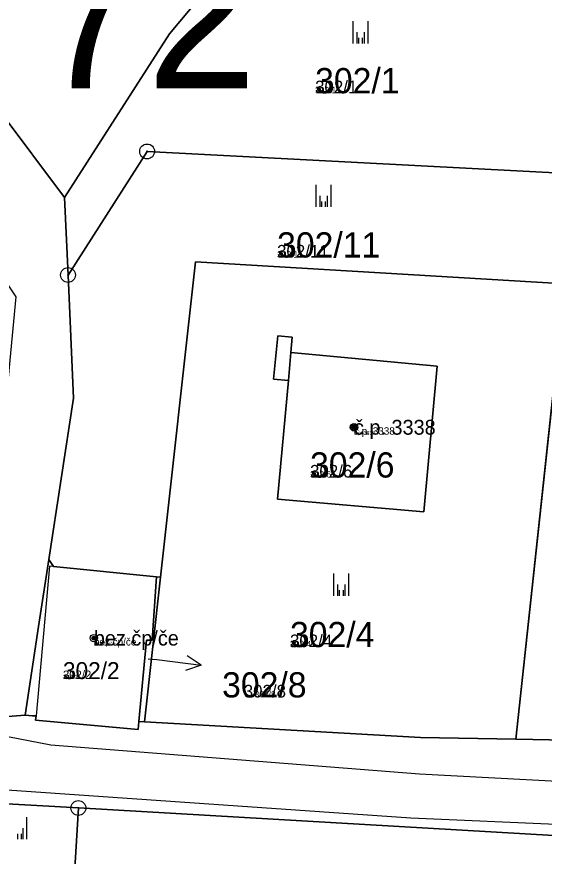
# Model space of a CAD drawing. Extents: x -759873 to -758487, y -975024 to -973516.
# Drawn here: x -759035.8 to -759000.3, y -974362.2 to -974305.6 of the extents above; entities that cross this region are included whole.
import ezdxf

# ---------------------------------------------------------------- set-up
doc = ezdxf.new("R2010")
doc.units = 0
for name, color, linetype in [('KAT_02_hranice parcel', 7, 'Continuous'), ('KAT_03_1000_st čísla parcelní', 7, 'Continuous'), ('KAT_03_1000_čísla parcelní', 7, 'Continuous'), ('KAT_03_1000_čísla popisná', 7, 'Continuous'), ('KAT_03_250_st čísla parcelní', 7, 'Continuous'), ('KAT_03_250_čísla parcelní', 7, 'Continuous'), ('KAT_03_250_čísla popisná', 7, 'Continuous'), ('KAT_03_500_st čísla parcelní', 7, 'Continuous'), ('KAT_03_500_čísla parcelní', 7, 'Continuous'), ('KAT_03_500_čísla popisná', 7, 'Continuous'), ('KAT_04_vnitřní kresba', 7, 'Continuous'), ('KAT_05_1000_značky kultur', 7, 'Continuous'), ('KAT_05_250_značky kultur', 7, 'Continuous'), ('KAT_05_500_značky kultur', 7, 'Continuous'), ('KAT_07_1000_značky budov', 7, 'Continuous'), ('KAT_07_250_značky budov', 7, 'Continuous'), ('KAT_07_500_značky budov', 7, 'Continuous'), ('KAT_11_značky bodu BP', 7, 'Continuous'), ('KAT_12_pomocná šipka', 7, 'Continuous'), ('KAT_13_popis', 7, 'Continuous'), ('KAT_14_plocha_budovy', 7, 'Continuous'), ('KAT_14_plocha_pozemek', 7, 'Continuous')]:
    doc.layers.add(name, color=color, linetype=linetype)

msp = doc.modelspace()

# ---------------------------------------------------------------- linework, layer by layer
at = {"layer": 'KAT_02_hranice parcel'}
for p, q in [((-759032.56, -974317.79), (-759032.33, -974323.02)), ((-758998.87, -974323.61), (-759002.18, -974354.31)), ((-759026.1, -974343.38), (-759026.37, -974343.35)), ((-759026.1, -974343.38), (-759027.18, -974353.14)), ((-759035.22, -974352.69), (-759041.4, -974353.16)), ((-759027.18, -974353.14), (-759027.55, -974353.12)), ((-758977.12, -974354.79), (-759002.18, -974354.31))]:
    msp.add_line(p, q, dxfattribs=at)
for points in [[(-759057.23, -974110.82), (-759070.93, -974124.94), (-759074.88, -974130.5), (-759080.81, -974167.04), (-759083.49, -974196.85), (-759080.01, -974222.92), (-759077.81, -974236.38), (-759067.25, -974271.4), (-759032.56, -974317.79)], [(-759014.33, -974293.41), (-759025.5, -974306.76), (-759032.56, -974317.79)], [(-759032.33, -974323.02), (-759027, -974314.69), (-758998.23, -974316.19)], [(-758998.87, -974323.61), (-759023.75, -974322.12), (-759026.1, -974343.38)], [(-759032.33, -974323.02), (-759031.96, -974331.33), (-759033.62, -974342.2)], [(-759017.23, -974327.21), (-759017.32, -974328.25), (-759007.46, -974329.16), (-759008.36, -974338.99), (-759018.21, -974338.13), (-759017.49, -974330.13), (-759018.49, -974330.04), (-759018.19, -974327.12), (-759017.23, -974327.21)], [(-759035.22, -974352.69), (-759034.31, -974346.71), (-759033.62, -974342.2)], [(-759026.37, -974343.35), (-759033.3, -974342.67), (-759033.62, -974342.2)], [(-759027.55, -974353.12), (-759027.05, -974347.62), (-759026.67, -974347.64), (-759026.37, -974343.35)], [(-759027.55, -974353.12), (-759027.6, -974353.65), (-759034.51, -974353.02), (-759034.48, -974352.73), (-759034.72, -974352.72), (-759035.22, -974352.69)], [(-759002.18, -974354.31), (-759008.59, -974354.19), (-759027.18, -974353.14)], [(-759031.63, -974358.94), (-759032.43, -974372.28), (-759040.64, -974371.84), (-759039.97, -974358.1)], [(-759039.97, -974358.1), (-759037.67, -974358.59), (-759031.63, -974358.94)], [(-759031.63, -974358.94), (-758978.01, -974362.06), (-758930.04, -974363.17)]]:
    msp.add_lwpolyline(points, dxfattribs=at)
at = {"layer": 'KAT_03_1000_čísla popisná'}
for centre in [(-759013.07, -974333.28), (-759030.59, -974347.49)]:
    msp.add_circle(centre, 0.25, dxfattribs=at)
at = {"layer": 'KAT_03_250_čísla popisná'}
for centre in [(-759013.07, -974333.28), (-759030.59, -974347.49)]:
    msp.add_circle(centre, 0.0625, dxfattribs=at)
at = {"layer": 'KAT_03_500_čísla popisná'}
for centre in [(-759013.07, -974333.28), (-759030.59, -974347.49)]:
    msp.add_circle(centre, 0.125, dxfattribs=at)
at = {"layer": 'KAT_04_vnitřní kresba'}
for p, q in [((-759017.49, -974330.13), (-759017.32, -974328.25)), ((-759033.57, -974342.64), (-759034.48, -974352.73)), ((-759033.3, -974342.67), (-759033.57, -974342.64)), ((-759041.4, -974353.16), (-759033.48, -974354.69)), ((-759033.48, -974354.69), (-759008.66, -974356.64)), ((-759008.66, -974356.64), (-758988.32, -974357.74)), ((-759040.71, -974357.41), (-759009.25, -974359.61)), ((-759009.25, -974359.61), (-758949.37, -974362.15))]:
    msp.add_line(p, q, dxfattribs=at)
at = {"layer": 'KAT_05_1000_značky kultur'}
for p, q in [((-759013.121, -974307.41), (-759013.121, -974305.91)), ((-759012.12, -974307.41), (-759012.12, -974305.91)), ((-759015.611, -974318.43), (-759015.611, -974316.93)), ((-759014.61, -974318.43), (-759014.61, -974316.93)), ((-759014.421, -974344.63), (-759014.421, -974343.13)), ((-759013.42, -974344.63), (-759013.42, -974343.13)), ((-759035.1, -974361.05), (-759035.1, -974359.55))]:
    msp.add_line(p, q, dxfattribs=at)
at = {"layer": 'KAT_05_250_značky kultur'}
for p, q in [((-759012.738, -974307.41), (-759012.738, -974307.035)), ((-759012.488, -974307.41), (-759012.488, -974307.035)), ((-759015.228, -974318.43), (-759015.228, -974318.055)), ((-759014.978, -974318.43), (-759014.978, -974318.055)), ((-759014.038, -974344.63), (-759014.038, -974344.255)), ((-759013.787, -974344.63), (-759013.787, -974344.255)), ((-759035.718, -974361.05), (-759035.718, -974360.675)), ((-759035.468, -974361.05), (-759035.468, -974360.675))]:
    msp.add_line(p, q, dxfattribs=at)
at = {"layer": 'KAT_05_500_značky kultur'}
for p, q in [((-759012.866, -974307.41), (-759012.866, -974306.66)), ((-759012.365, -974307.41), (-759012.365, -974306.66)), ((-759015.356, -974318.43), (-759015.356, -974317.68)), ((-759014.855, -974318.43), (-759014.855, -974317.68)), ((-759014.166, -974344.63), (-759014.166, -974343.88)), ((-759013.665, -974344.63), (-759013.665, -974343.88)), ((-759035.345, -974361.05), (-759035.345, -974360.3))]:
    msp.add_line(p, q, dxfattribs=at)
at = {"layer": 'KAT_07_1000_značky budov'}
for centre, radius in [((-759013.077, -974333.279), 0.175), ((-759030.595, -974347.489), 0.117)]:
    msp.add_circle(centre, radius, dxfattribs=at)
at = {"layer": 'KAT_07_250_značky budov'}
for centre, radius in [((-759013.072, -974333.28), 0.0437), ((-759030.591, -974347.49), 0.0293)]:
    msp.add_circle(centre, radius, dxfattribs=at)
at = {"layer": 'KAT_07_500_značky budov'}
for centre, radius in [((-759013.073, -974333.28), 0.0875), ((-759030.592, -974347.49), 0.0586)]:
    msp.add_circle(centre, radius, dxfattribs=at)
at = {"layer": 'KAT_11_značky bodu BP'}
for centre, radius in [((-759027, -974314.69), 0.5), ((-759027, -974314.69), 0.0303), ((-759032.33, -974323.02), 0.5), ((-759032.33, -974323.02), 0.0303), ((-759031.63, -974358.94), 0.5), ((-759031.63, -974358.94), 0.0303)]:
    msp.add_circle(centre, radius, dxfattribs=at)
at = {"layer": 'KAT_12_pomocná šipka'}
for p, q in [((-759026.94, -974348.88), (-759026.34, -974348.94)), ((-759026.34, -974348.94), (-759023.361, -974349.306)), ((-759023.361, -974349.306), (-759024.294, -974348.687)), ((-759023.361, -974349.306), (-759024.416, -974349.681))]:
    msp.add_line(p, q, dxfattribs=at)
at = {"layer": 'KAT_14_plocha_budovy'}
for points in [[(-759018.21, -974338.13), (-759008.36, -974338.99), (-759007.46, -974329.16), (-759017.32, -974328.25), (-759017.49, -974330.13)], [(-759034.51, -974353.02), (-759027.6, -974353.65), (-759027.55, -974353.12), (-759027.05, -974347.62), (-759026.67, -974347.64), (-759026.37, -974343.35), (-759033.3, -974342.67), (-759033.57, -974342.64), (-759034.48, -974352.73)]]:
    msp.add_lwpolyline(points, close=True, dxfattribs=at)
at = {"layer": 'KAT_14_plocha_pozemek'}
for points in [[(-759077.81, -974236.38), (-759067.25, -974271.4), (-759032.56, -974317.79), (-759025.5, -974306.76), (-759014.33, -974293.41), (-759017.69, -974290.39), (-759006.93, -974283.66), (-759032.75, -974249.27), (-759049.48, -974222.24), (-759060.12, -974196.25), (-759061.42, -974162.34), (-759060.75, -974132.98), (-759057.23, -974110.82), (-759070.93, -974124.94), (-759074.88, -974130.5), (-759080.81, -974167.04), (-759083.49, -974196.85), (-759080.01, -974222.92)], [(-758997.18, -974304.01), (-759014.33, -974293.41), (-759025.5, -974306.76), (-759032.56, -974317.79), (-759032.33, -974323.02), (-759027, -974314.69), (-758998.23, -974316.19)], [(-759026.1, -974343.38), (-759023.75, -974322.12), (-758998.87, -974323.61), (-758998.23, -974316.19), (-759027, -974314.69), (-759032.33, -974323.02), (-759031.96, -974331.33), (-759033.62, -974342.2), (-759033.3, -974342.67), (-759026.37, -974343.35)], [(-759026.1, -974343.38), (-759027.18, -974353.14), (-759008.59, -974354.19), (-759002.18, -974354.31), (-758998.87, -974323.61), (-759023.75, -974322.12)], [(-758973.99, -974325.11), (-758998.87, -974323.61), (-759002.18, -974354.31), (-758977.12, -974354.79), (-758975.05, -974336.27)], [(-759017.23, -974327.21), (-759017.32, -974328.25), (-759007.46, -974329.16), (-759008.36, -974338.99), (-759018.21, -974338.13), (-759017.49, -974330.13), (-759018.49, -974330.04), (-759018.19, -974327.12)], [(-759017.23, -974327.21), (-759018.19, -974327.12), (-759018.49, -974330.04), (-759017.49, -974330.13), (-759018.21, -974338.13), (-759008.36, -974338.99), (-759007.46, -974329.16), (-759017.32, -974328.25)], [(-759026.37, -974343.35), (-759033.3, -974342.67), (-759033.62, -974342.2), (-759034.31, -974346.71), (-759035.22, -974352.69), (-759034.72, -974352.72), (-759034.48, -974352.73), (-759034.51, -974353.02), (-759027.6, -974353.65), (-759027.55, -974353.12), (-759027.05, -974347.62), (-759026.67, -974347.64)], [(-759026.1, -974343.38), (-759026.37, -974343.35), (-759026.67, -974347.64), (-759027.05, -974347.62), (-759027.55, -974353.12), (-759027.18, -974353.14)], [(-759040.64, -974371.84), (-759039.97, -974358.1), (-759051.14, -974355.72), (-759056.37, -974366.99), (-759057.32, -974369.03), (-759044.21, -974373.31), (-759031.64, -974374.99), (-759025.9, -974373.3), (-759018.27, -974368.4), (-759006.26, -974363.99), (-758992.93, -974364.06), (-758971.41, -974365.53), (-758952.35, -974369.35), (-758911.81, -974379.4), (-758867.55, -974396.24), (-758881.44, -974386.63), (-758930.04, -974363.17), (-758978.01, -974362.06), (-759031.63, -974358.94), (-759032.43, -974372.28)], [(-759039.97, -974358.1), (-759040.64, -974371.84), (-759032.43, -974372.28), (-759031.63, -974358.94), (-759037.67, -974358.59)]]:
    msp.add_lwpolyline(points, close=True, dxfattribs=at)
for points in [[(-759088.06, -974196.14), (-759086.81, -974208.04), (-759084.6, -974223.26), (-759081.12, -974237.92), (-759079.79, -974238.96), (-759070.66, -974272.52), (-759048.01, -974306.32), (-759035.84, -974324.49), (-759036.24, -974328.76), (-759037.74, -974344.49), (-759041.4, -974353.16), (-759035.22, -974352.69), (-759034.31, -974346.71), (-759033.62, -974342.2), (-759031.96, -974331.33), (-759032.33, -974323.02), (-759032.56, -974317.79), (-759067.25, -974271.4), (-759077.81, -974236.38), (-759080.01, -974222.92), (-759083.49, -974196.85)], [(-759228.43, -974270.82), (-759182.46, -974265.89), (-759176.65, -974264.97), (-759164.95, -974263.13), (-759162.53, -974263.23), (-759159.62, -974263.35), (-759148.86, -974268.28), (-759137.55, -974276.08), (-759137.41, -974276.19), (-759133.42, -974279.5), (-759126.27, -974285.42), (-759121.65, -974289.25), (-759113.88, -974295.69), (-759108.36, -974300.77), (-759091.71, -974319.84), (-759079.48, -974333.82), (-759074.99, -974338.96), (-759070.5, -974344.1), (-759060.98, -974351.22), (-759051.14, -974355.72), (-759039.97, -974358.1), (-759037.67, -974358.59), (-759031.63, -974358.94), (-758978.01, -974362.06)], [(-758977.12, -974354.79), (-759002.18, -974354.31), (-759008.59, -974354.19), (-759027.18, -974353.14), (-759027.55, -974353.12), (-759027.6, -974353.65), (-759034.51, -974353.02), (-759034.48, -974352.73), (-759034.72, -974352.72), (-759035.22, -974352.69), (-759041.4, -974353.16), (-759052.29, -974349.95), (-759056.77, -974347.39), (-759057.86, -974346.77), (-759064.23, -974342.47), (-759072.66, -974333.02), (-759085.69, -974318.34), (-759087.77, -974316.01), (-759090.1, -974313.42), (-759098.18, -974304.42)]]:
    msp.add_lwpolyline(points, dxfattribs=at)

# ---------------------------------------------------------------- texts
at = {"layer": 'KAT_03_1000_st čísla parcelní'}
for s, height, p in [('302/6', 1.7, (-759016.03, -974336.669)), ('302/2', 1.14, (-759032.67, -974350.25))]:
    msp.add_text(s, height=height, dxfattribs=at).set_placement(p)
at = {"layer": 'KAT_03_1000_čísla parcelní'}
for s, p in [('302/1', (-759015.69, -974310.77)), ('302/11', (-759018.25, -974321.84)), ('302/4', (-759017.38, -974348.1)), ('302/8', (-759021.953, -974351.49))]:
    msp.add_text(s, height=1.7, dxfattribs=at).set_placement(p)
at = {"layer": 'KAT_03_1000_čísla popisná'}
for s, p in [('č.p. 3338', (-759013.07, -974333.78)), ('bez čp/če', (-759030.59, -974347.99))]:
    msp.add_text(s, height=1, dxfattribs=at).set_placement(p)
at = {"layer": 'KAT_03_250_st čísla parcelní'}
for s, height, p in [('302/6', 0.425, (-759016.03, -974336.669)), ('302/2', 0.285, (-759032.67, -974350.25))]:
    msp.add_text(s, height=height, dxfattribs=at).set_placement(p)
at = {"layer": 'KAT_03_250_čísla parcelní'}
for s, p in [('302/1', (-759015.69, -974310.77)), ('302/11', (-759018.25, -974321.84)), ('302/4', (-759017.38, -974348.1)), ('302/8', (-759019.765, -974351.49))]:
    msp.add_text(s, height=0.425, dxfattribs=at).set_placement(p)
at = {"layer": 'KAT_03_250_čísla popisná'}
for s, p in [('č.p. 3338', (-759013.07, -974333.78)), ('bez čp/če', (-759030.59, -974347.99))]:
    msp.add_text(s, height=0.25, dxfattribs=at).set_placement(p)
at = {"layer": 'KAT_03_500_st čísla parcelní'}
for s, height, p in [('302/6', 0.85, (-759016.03, -974336.669)), ('302/2', 0.57, (-759032.67, -974350.25))]:
    msp.add_text(s, height=height, dxfattribs=at).set_placement(p)
at = {"layer": 'KAT_03_500_čísla parcelní'}
for s, p in [('302/1', (-759015.69, -974310.77)), ('302/11', (-759018.25, -974321.84)), ('302/4', (-759017.38, -974348.1)), ('302/8', (-759020.494, -974351.49))]:
    msp.add_text(s, height=0.85, dxfattribs=at).set_placement(p)
at = {"layer": 'KAT_03_500_čísla popisná'}
for s, p in [('č.p. 3338', (-759013.07, -974333.78)), ('bez čp/če', (-759030.59, -974347.99))]:
    msp.add_text(s, height=0.5, dxfattribs=at).set_placement(p)
at = {"layer": 'KAT_13_popis'}
msp.add_text('Dobětice 757772', height=10, dxfattribs=at).set_placement((-759120.712, -974310.427))

doc.saveas('drawing.dxf')
